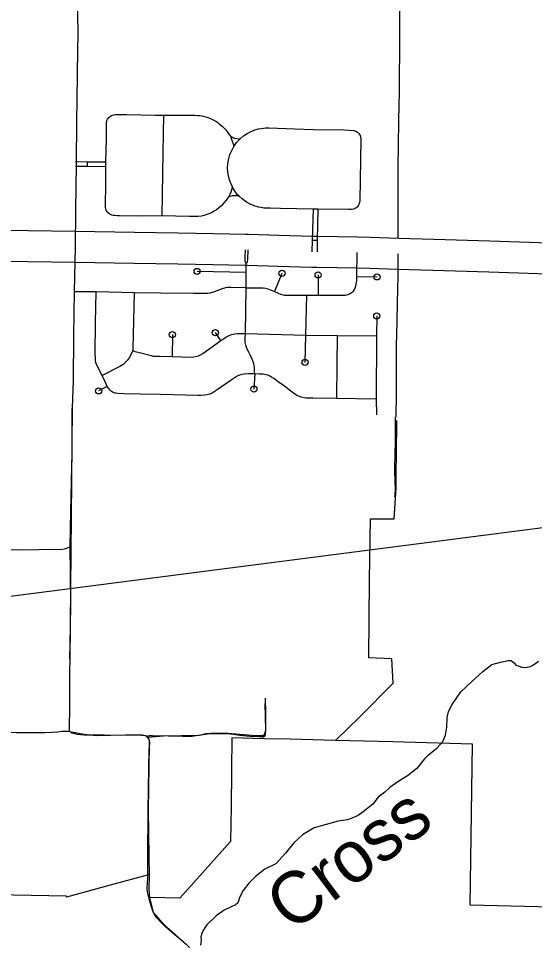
# Model space of a CAD drawing. Extents: x 670147 to 673275, y 705573 to 707613.
# Drawn here: x 671394.4 to 671478.7, y 706253.2 to 706403.8 of the extents above; entities that cross this region are included whole.
import ezdxf

# ---------------------------------------------------------------- set-up
doc = ezdxf.new("R2010")
doc.units = 0
for name, color, linetype in [('10', 7, 'Continuous'), ('32', 7, 'Continuous'), ('33', 7, 'Continuous'), ('34', 7, 'Continuous'), ('35', 7, 'Continuous'), ('45', 7, 'Continuous'), ('6', 7, 'Continuous'), ('Default', 7, 'Continuous')]:
    doc.layers.add(name, color=color, linetype=linetype)

msp = doc.modelspace()

# ---------------------------------------------------------------- linework, layer by layer
at = {"layer": '10'}
for points in [[(671482.72, 706367.02), (671471.44, 706367.41), (671462.29, 706367.69), (671456.49, 706367.86), (671451.91, 706368.01), (671449.81, 706368.06), (671443.25, 706368.18), (671442.42, 706368.18), (671436.95, 706368.36), (671431.98, 706368.5), (671431.48, 706368.51), (671426.29, 706368.62), (671420.52, 706368.72), (671413.36, 706368.82), (671403.69, 706368.99), (671396.01, 706369.1), (671386.04, 706369.14)], [(671386.01, 706364.14), (671395.96, 706364.1), (671403.61, 706363.99), (671413.28, 706363.82), (671420.44, 706363.72), (671426.2, 706363.62), (671431.37, 706363.51), (671431.85, 706363.5), (671436.8, 706363.36), (671442.32, 706363.19), (671443.18, 706363.18), (671449.71, 706363.06), (671451.77, 706363.01), (671456.33, 706362.87), (671462.14, 706362.69), (671471.28, 706362.42), (671482.56, 706362.02)]]:
    msp.add_lwpolyline(points, dxfattribs=at)
at = {"layer": '32'}
for points in [[(671402.8, 706299.16), (671402.91, 706304.36), (671402.94, 706308.16), (671402.91, 706313.15), (671402.88, 706317.47), (671402.97, 706323.24), (671403.17, 706332.88), (671403.2, 706340.07)], [(671455.93, 706325.67), (671455.95, 706325.93), (671455.99, 706327.01), (671455.95, 706328), (671455.95, 706328.73), (671455.93, 706329.45), (671455.91, 706330.56), (671455.95, 706332.27), (671456.03, 706334.99), (671456.01, 706336.52), (671456.04, 706338.68)], [(671421.81, 706252.54), (671420.96, 706253.29), (671419.65, 706254.36), (671418.33, 706255.55), (671417.61, 706256.25), (671417.04, 706256.87), (671416.68, 706257.33), (671416.4, 706257.89), (671416.11, 706258.86), (671415.77, 706259.97), (671415.55, 706260.88), (671415.45, 706261.5), (671415.45, 706261.84), (671415.5, 706262.49), (671415.52, 706263.32), (671415.53, 706266.83), (671415.59, 706274.36), (671415.73, 706281.41), (671415.79, 706284.36), (671415.85, 706285.42), (671415.82, 706285.85), (671415.68, 706286.2), (671415.42, 706286.45), (671415.19, 706286.63), (671414.59, 706286.68), (671408.4, 706286.71), (671405.22, 706286.71), (671403.98, 706286.83), (671403.14, 706287.07), (671402.98, 706287.18), (671402.87, 706287.28)]]:
    msp.add_lwpolyline(points, dxfattribs=at)
at = {"layer": '33'}
for points in [[(671404.26, 706444.11), (671404.17, 706437.44), (671404.18, 706436.97), (671404.18, 706433.84), (671404.18, 706429.33), (671404.18, 706426.95), (671404.23, 706422.05), (671404.21, 706420.18), (671404.2, 706416.8), (671404.2, 706413.25), (671404.2, 706411.68), (671404.15, 706409.02), (671404.08, 706404.82), (671404.09, 706400.94), (671404.08, 706398.84), (671404.02, 706394.56), (671403.91, 706386.83), (671403.86, 706380.37), (671403.85, 706379.55), (671403.79, 706376.56), (671403.74, 706372.26), (671403.65, 706366.49)], [(671428.75, 706374.65), (671428.37, 706374.13), (671427.99, 706373.66), (671427.61, 706373.22), (671427.16, 706372.85), (671426.77, 706372.55), (671426.4, 706372.31), (671425.94, 706372.07), (671425.49, 706371.88), (671425.18, 706371.76), (671424.76, 706371.63), (671424.3, 706371.53), (671423.72, 706371.47), (671423.21, 706371.43), (671422.35, 706371.43), (671417.84, 706371.56), (671413.96, 706371.52), (671410.94, 706371.56), (671410.55, 706371.58), (671410.17, 706371.6), (671409.89, 706371.62), (671409.67, 706371.69), (671409.36, 706371.83), (671409.08, 706372.03), (671408.91, 706372.24), (671408.75, 706372.47), (671408.66, 706372.71), (671408.62, 706372.99), (671408.62, 706373.28), (671408.67, 706376.68), (671408.66, 706379.56), (671408.68, 706380.34), (671408.77, 706384.11), (671408.8, 706386.62), (671408.86, 706387.11), (671408.96, 706387.35), (671409.16, 706387.62), (671409.47, 706387.85), (671409.74, 706388), (671409.97, 706388.08), (671410.2, 706388.12), (671410.57, 706388.12), (671412.03, 706388.09), (671416.75, 706387.99), (671418.09, 706387.99)], [(671418.09, 706387.99), (671417.98, 706381.92), (671417.84, 706371.56)], [(671418.09, 706387.99), (671421.22, 706388.01), (671423.24, 706388), (671423.67, 706387.97), (671424.02, 706387.94), (671424.36, 706387.89), (671424.65, 706387.82), (671425, 706387.75), (671425.35, 706387.65), (671425.79, 706387.46), (671426.2, 706387.26), (671426.64, 706387), (671426.96, 706386.79), (671427.28, 706386.54), (671427.73, 706386.15), (671428.16, 706385.72), (671428.45, 706385.37), (671428.73, 706385), (671429.12, 706384.44)], [(671429.59, 706382.86), (671430.06, 706383.53), (671430.56, 706384.11), (671431.18, 706384.62), (671431.78, 706385), (671432.43, 706385.36), (671433.04, 706385.6), (671433.61, 706385.75), (671434.12, 706385.84), (671434.75, 706385.91), (671435.34, 706385.91), (671439.59, 706385.77), (671442.57, 706385.68), (671447.58, 706385.6), (671449.22, 706385.52), (671449.52, 706385.41), (671449.8, 706385.21), (671450.02, 706385), (671450.23, 706384.69), (671450.31, 706384.42), (671450.36, 706384.13), (671450.3, 706380.72), (671450.21, 706374.07), (671450.15, 706373.72), (671449.96, 706373.28), (671449.74, 706372.99), (671449.44, 706372.76), (671449.14, 706372.66), (671448.77, 706372.6), (671448.34, 706372.58), (671443.31, 706372.63), (671442.55, 706372.65)], [(671430.56, 706384.11), (671430.37, 706384.11), (671430.09, 706384.15), (671429.76, 706384.21), (671429.44, 706384.32), (671429.25, 706384.39), (671429.12, 706384.44), (671429.19, 706384.19), (671429.34, 706383.75), (671429.48, 706383.31), (671429.55, 706383.04), (671429.59, 706382.86)], [(671442.55, 706372.65), (671437.24, 706372.76), (671435.52, 706372.81), (671434.49, 706372.84), (671434.06, 706372.9), (671433.61, 706373), (671432.91, 706373.22), (671432.27, 706373.49), (671431.69, 706373.8), (671430.98, 706374.32), (671430.45, 706374.76), (671430.16, 706375.07), (671429.83, 706375.52), (671429.43, 706376.11), (671429.32, 706376.38), (671429.03, 706376.99), (671428.87, 706377.44), (671428.71, 706378.04), (671428.6, 706378.73), (671428.56, 706379.34), (671428.6, 706380.13), (671428.79, 706380.95), (671428.95, 706381.56), (671429.31, 706382.32), (671429.59, 706382.86)], [(671408.68, 706380.34), (671405.64, 706380.33), (671403.73, 706380.37)], [(671408.66, 706379.56), (671405.64, 706379.63), (671403.75, 706379.61)], [(671405.64, 706380.33), (671405.64, 706379.63)], [(671429.32, 706376.38), (671429.25, 706375.95), (671429.12, 706375.45), (671428.97, 706375.07), (671428.85, 706374.84), (671428.75, 706374.65), (671429.02, 706374.79), (671429.38, 706374.87), (671429.91, 706374.9), (671430.12, 706374.87), (671430.45, 706374.76)], [(671442.55, 706372.65), (671442.42, 706367.57), (671442.37, 706365.69)], [(671443.31, 706372.63), (671443.2, 706367.56), (671443.22, 706365.68)], [(671442.42, 706367.57), (671443.2, 706367.56)], [(671403.65, 706366.49), (671403.49, 706359.17), (671403.41, 706351.94), (671403.34, 706344.6), (671403.2, 706340.18)], [(671431.43, 706366.01), (671431.41, 706364.8), (671431.39, 706364.41), (671431.41, 706364.16), (671431.46, 706364.02), (671431.53, 706363.9), (671431.62, 706363.81), (671431.71, 706363.86), (671431.83, 706363.98), (671431.86, 706364.1), (671431.89, 706364.44), (671431.92, 706366)], [(671431.6, 706359.81), (671434.37, 706359.78), (671434.8, 706359.74), (671435.18, 706359.64), (671436.25, 706359.19), (671437.2, 706358.79), (671437.63, 706358.67), (671437.89, 706358.62), (671438.14, 706358.6), (671438.5, 706358.6), (671441.52, 706358.58), (671443.36, 706358.6), (671447, 706358.6), (671447.78, 706358.61), (671448.23, 706358.7), (671448.52, 706358.82), (671448.82, 706359.01), (671449.13, 706359.27), (671449.32, 706359.52), (671449.45, 706359.79), (671449.52, 706360.08), (671449.59, 706360.46), (671449.68, 706360.95), (671449.71, 706361.63), (671449.76, 706365.56)], [(671456.41, 706365.36), (671456.41, 706361.69), (671456.29, 706357.36), (671456.23, 706354.31), (671456.13, 706350.3), (671456.11, 706345.89), (671456.11, 706342.56), (671456.05, 706338.68)], [(671431.59, 706362.33), (671423.6, 706362.48)], [(671433.03, 706345.74), (671433, 706346.16), (671432.97, 706346.68), (671432.9, 706347.14), (671432.87, 706347.41), (671432.76, 706347.73), (671432.57, 706348.16), (671432.25, 706348.87), (671431.99, 706349.4), (671431.72, 706349.91), (671431.54, 706350.43), (671431.47, 706350.86), (671431.46, 706351.58), (671431.49, 706352.32), (671431.6, 706359.81), (671431.59, 706362.33), (671431.62, 706363.29), (671431.62, 706363.81)], [(671437.47, 706362.16), (671436.25, 706359.19)], [(671443.37, 706361.92), (671443.36, 706358.6)], [(671449.71, 706361.63), (671453, 706361.59)], [(671431.6, 706359.81), (671429.09, 706359.88), (671428.52, 706359.83), (671428.23, 706359.78), (671427.71, 706359.65), (671426.96, 706359.36), (671426.24, 706359.09), (671425.67, 706358.94), (671425.3, 706358.9), (671424.79, 706358.87), (671422.98, 706358.87), (671417.59, 706358.93), (671413.3, 706359), (671407.11, 706359.13), (671403.49, 706359.17)], [(671408.91, 706343.66), (671408.55, 706344.46), (671408.07, 706345.47), (671407.16, 706347.28), (671407.04, 706347.59), (671406.98, 706347.91), (671406.97, 706348.31), (671406.93, 706349.03), (671406.99, 706354.08), (671407.11, 706359.13)], [(671413.3, 706359), (671413.12, 706349.9), (671413.08, 706349.55), (671413.01, 706349.37), (671412.78, 706348.88), (671412.49, 706348.35), (671412.18, 706347.91), (671411.87, 706347.58), (671411.51, 706347.29), (671410.95, 706346.95), (671408.07, 706345.47)], [(671441.25, 706347.62), (671441.36, 706352.07), (671441.52, 706358.58)], [(671452.95, 706355.22), (671452.92, 706351.97), (671452.87, 706341.6), (671452.89, 706339.06)], [(671413.08, 706349.55), (671413.45, 706349.41), (671413.96, 706349.27), (671416.09, 706348.72), (671416.44, 706348.64), (671416.79, 706348.63), (671417.45, 706348.63), (671419.54, 706348.57), (671422.61, 706348.48), (671423.09, 706348.53), (671423.53, 706348.61), (671423.83, 706348.7), (671424.15, 706348.85), (671424.52, 706349.08), (671427.47, 706351.21), (671427.98, 706351.53), (671428.39, 706351.82), (671428.81, 706352.03), (671429.24, 706352.18), (671429.78, 706352.3), (671430.21, 706352.34), (671430.69, 706352.35), (671431.49, 706352.32), (671441.36, 706352.07), (671446.48, 706351.99), (671452.92, 706351.97)], [(671419.56, 706352.15), (671419.54, 706348.57)], [(671427.47, 706351.21), (671426.58, 706352.48)], [(671446.48, 706351.99), (671446.41, 706347.26), (671446.37, 706341.7)], [(671452.87, 706341.6), (671446.37, 706341.7), (671442.53, 706341.77), (671441.44, 706341.79), (671441.11, 706341.85), (671440.6, 706341.96), (671440.02, 706342.17), (671439.59, 706342.45), (671438.89, 706342.93), (671437.88, 706343.71), (671436.87, 706344.47), (671436.14, 706344.98), (671435.78, 706345.22), (671435.46, 706345.39), (671435.16, 706345.53), (671434.82, 706345.61), (671434.37, 706345.7), (671433.78, 706345.72), (671433.03, 706345.74), (671431.99, 706345.77), (671431.3, 706345.72), (671430.93, 706345.66), (671430.5, 706345.53), (671430.16, 706345.36), (671429.8, 706345.14), (671429.14, 706344.71), (671426.86, 706343.16), (671426.06, 706342.62), (671425.67, 706342.44), (671425.26, 706342.31), (671424.79, 706342.24), (671424.2, 706342.2), (671423.71, 706342.22), (671417.63, 706342.35), (671414.29, 706342.42), (671411.69, 706342.49), (671410.64, 706342.53), (671410.32, 706342.57), (671410.14, 706342.58), (671409.87, 706342.72), (671409.63, 706342.87), (671409.38, 706343.1), (671408.91, 706343.66)], [(671433.03, 706345.74), (671432.88, 706343.25)], [(671408.91, 706343.66), (671407.51, 706342.96)]]:
    msp.add_lwpolyline(points, dxfattribs=at)
for centre in [(671423.6, 706362.48), (671437.47, 706362.16), (671443.37, 706361.92), (671453, 706361.59), (671419.56, 706352.15), (671426.58, 706352.48), (671441.25, 706347.62), (671407.51, 706342.96), (671432.88, 706343.25)]:
    msp.add_circle(centre, 0.5, dxfattribs=at)
at = {"layer": '34'}
msp.add_line((671403.2, 706340.18), (671402.8, 706298.88), dxfattribs=at)
for points in [[(671402.8, 706298.88), (671402.77, 706297.36), (671402.77, 706291.84), (671402.72, 706287.33)], [(671415.55, 706286.41), (671418.1, 706286.6), (671423.93, 706286.71), (671425.88, 706287.05), (671428.69, 706287.05), (671433.12, 706286.65), (671434.41, 706286.65), (671434.69, 706286.94), (671434.81, 706287.58), (671434.72, 706291.9)], [(671402.79, 706287.33), (671402.01, 706287.35), (671401.52, 706287.32), (671400.78, 706287.22), (671399.92, 706287.14), (671398.74, 706287.12), (671397.07, 706287.11), (671394.05, 706287.12), (671390.81, 706287.16), (671387.53, 706287.21), (671382.87, 706287.25), (671380.24, 706287.25), (671378.74, 706287.25), (671375.75, 706287.28), (671371.96, 706287.31), (671368.13, 706287.34), (671363.3, 706287.37), (671359.16, 706287.34), (671354.83, 706287.32), (671350.6, 706287.44)], [(671402.79, 706287.33), (671405.07, 706286.88), (671407.1, 706286.68), (671414.28, 706286.83), (671415.23, 706286.7), (671415.55, 706286.41), (671415.79, 706285.96), (671415.77, 706285.22), (671415.61, 706274.54), (671415.7, 706266.9), (671415.75, 706263.94), (671415.71, 706261.44), (671415.84, 706260.19), (671416.43, 706257.74), (671417.59, 706256.39), (671418.67, 706255.35), (671421.9, 706252.46), (671423.55, 706250.76), (671424.14, 706249.81), (671424.66, 706248.29), (671426.54, 706244.07)]]:
    msp.add_lwpolyline(points, dxfattribs=at)
at = {"layer": '35'}
for points in [[(671460.73, 706282.87), (671461.39, 706283.5), (671462.82, 706284.67), (671463.77, 706285.69), (671464.19, 706286.71), (671464.38, 706288.04), (671464.44, 706289.57), (671464.7, 706290.62), (671465.3, 706291.76), (671466.7, 706293.83), (671468.48, 706295.51), (671470.26, 706297.13), (671471.78, 706298.27), (671473.18, 706298.66), (671474.42, 706298.94), (671474.86, 706298.94), (671475.15, 706298.78), (671475.47, 706298.5), (671475.69, 706298.18), (671476.23, 706297.99), (671476.67, 706297.83), (671477.28, 706297.77), (671478.1, 706297.96), (671478.58, 706298.21), (671479.37, 706298.82)], [(671460.73, 706282.87), (671459.51, 706281.26), (671458, 706280.11), (671456.39, 706279.13), (671455.08, 706278.17), (671454.26, 706277.42), (671453.21, 706276.6), (671452.32, 706275.48), (671450.75, 706274.23), (671449.89, 706273.61), (671449.17, 706273.28), (671448.15, 706272.92), (671446.64, 706272.69), (671442.72, 706271.59), (671440.81, 706270.47), (671439.4, 706269.12), (671438.05, 706267.45), (671436.48, 706265.71), (671434.67, 706264.82), (671433.12, 706263.62), (671432.05, 706262.55), (671431.12, 706261.35), (671430.56, 706260.33), (671430.4, 706259.83), (671430.25, 706259.32), (671429.85, 706259.01), (671429.18, 706258.69), (671428.03, 706258.14), (671426.73, 706257.23), (671425.21, 706255.72), (671424.63, 706254.93), (671424.35, 706254.32), (671424.22, 706253.78), (671424.24, 706253.32), (671424.15, 706252.43)]]:
    msp.add_lwpolyline(points, dxfattribs=at)
msp.add_circle((671452.95, 706355.22), 0.5, dxfattribs=at)
at = {"layer": '45'}
for points in [[(671379.29, 706314.28), (671379.54, 706314.26), (671379.87, 706314.28), (671380.21, 706314.36), (671380.5, 706314.49), (671381.05, 706314.88), (671382.04, 706315.65), (671382.91, 706316.31), (671383.54, 706316.71), (671384.02, 706316.94), (671384.39, 706317.09), (671384.66, 706317.16), (671385.19, 706317.2), (671388.21, 706317.15), (671391.74, 706317.08), (671394.78, 706317.02), (671397.72, 706317.08), (671399.93, 706317.09), (671401.34, 706317.08), (671401.91, 706317.17), (671402.44, 706317.35), (671402.71, 706317.43), (671402.88, 706317.47)], [(671434.74, 706292.75), (671434.75, 706290.38), (671434.75, 706287.54), (671434.72, 706286.89), (671434.64, 706286.67), (671434.55, 706286.5), (671434.4, 706286.42), (671434.25, 706286.41), (671433.73, 706286.44), (671432.23, 706286.51), (671430.59, 706286.68), (671429.51, 706286.85), (671428.33, 706286.94), (671426.51, 706286.94), (671425.36, 706286.97), (671424.98, 706286.94), (671424.63, 706286.86), (671424.17, 706286.74), (671423.45, 706286.6), (671422.72, 706286.53), (671421.29, 706286.53), (671418.91, 706286.54), (671416.33, 706286.62), (671415.79, 706286.6), (671415.62, 706286.57), (671415.42, 706286.45)]]:
    msp.add_lwpolyline(points, dxfattribs=at)
at = {"layer": '6'}
for points in [[(671456.79, 706418.2), (671456.6, 706392.09), (671456.61, 706391.77), (671456.51, 706387.26), (671456.43, 706382.87), (671456.41, 706379.65), (671456.41, 706376.41), (671456.41, 706373.14), (671456.42, 706367.96)], [(671446.25, 706285.89), (671450.14, 706289.65), (671455.61, 706295.2), (671455.43, 706299.22), (671451.66, 706299.35), (671451.78, 706312.1), (671451.94, 706322.06), (671455.8, 706322.06), (671456.1, 706327.14), (671456.2, 706335.11), (671456.21, 706335.54), (671456.24, 706338.12)], [(671446.22, 706285.86), (671438.82, 706286.05), (671434.62, 706286.15), (671429.26, 706286.29), (671429.2, 706281.06), (671429.2, 706280.87), (671429.14, 706275.04), (671429.08, 706269.34), (671420.8, 706260.11), (671415.95, 706260.19)], [(671507.36, 706231.95), (671507.52, 706241.68), (671507.61, 706247.14), (671507.67, 706250.67), (671507.79, 706258.02), (671498.29, 706258.2), (671494.58, 706258.27), (671481.52, 706258.61), (671468.24, 706258.94), (671468.6, 706285.24), (671455.58, 706285.63), (671446.22, 706285.86)], [(671415.68, 706263.92), (671409.97, 706262.38), (671402.24, 706260.28), (671402.24, 706260.41), (671376.28, 706260.92), (671375.97, 706260.91), (671367.53, 706260.74), (671366.38, 706260.71), (671364.71, 706260.73), (671363.04, 706260.74), (671361.37, 706260.76), (671360.43, 706260.81), (671360.31, 706244.87), (671360.39, 706242.75), (671359.99, 706240.86)]]:
    msp.add_lwpolyline(points, dxfattribs=at)
at = {"layer": 'Default'}
msp.add_line((671069.5, 706267.64), (671601.78, 706336.35), dxfattribs=at)

# ---------------------------------------------------------------- texts
at = {"layer": '35'}
msp.add_text('Cross', height=8.448, rotation=36.8958, dxfattribs=at).set_placement((671439.04, 706254.37))

doc.saveas('drawing.dxf')
